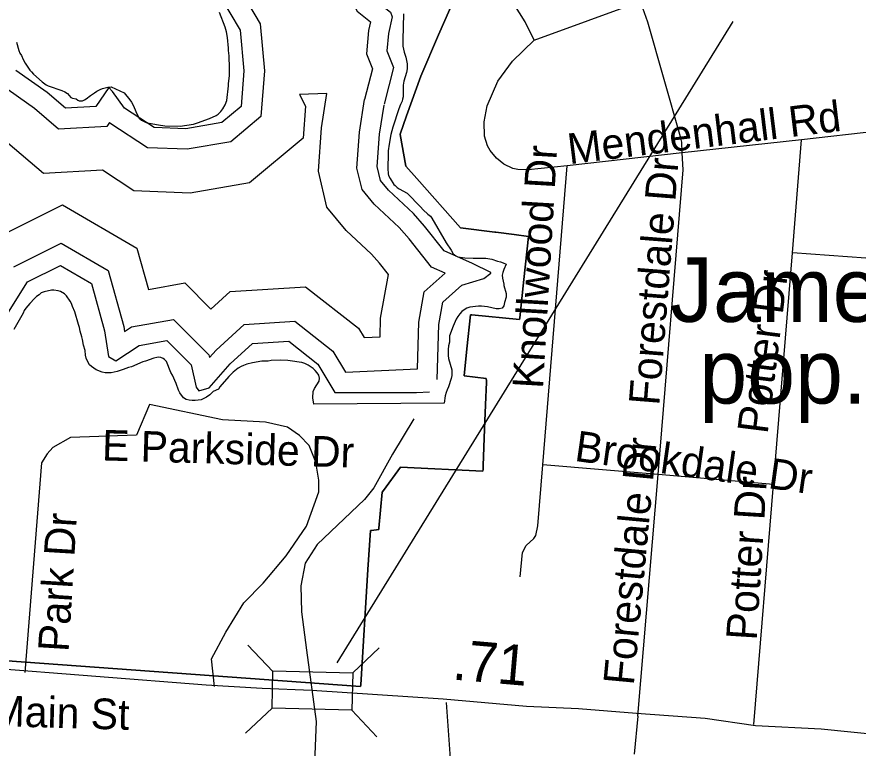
# Model space of a CAD drawing. Extents: x 1662474 to 1856135, y 779280 to 917889.
# Drawn here: x 1719362 to 1721976, y 817423 to 819694 of the extents above; entities that cross this region are included whole.
import ezdxf

# ---------------------------------------------------------------- set-up
doc = ezdxf.new("R2010")
doc.units = 0
for name, color, linetype in [('Exist Boundary Political City Limit New', 7, 'Continuous'), ('Exist Civil Demographics City Label', 7, 'Continuous'), ('Exist Hydrographic Buffer Line', 7, 'Continuous'), ('Exist Hydrographic Creek Single Shore', 7, 'Continuous'), ('Exist Hydrographic Lake Shore', 7, 'Continuous'), ('Exist Road Non-System Type 51', 7, 'Continuous'), ('Exist Road Non-System Type 51 Label', 7, 'Continuous'), ('Exist Road Secondary Mileage Hundredths English Label', 7, 'Continuous'), ('Exist Road Secondary Structure Standard Bridge CELL', 7, 'Continuous'), ('Exist Road Secondary Structure Standard Bridge Number Label', 7, 'Continuous'), ('Exist Road Secondary Type 51 Attributed', 7, 'Continuous'), ('Exist Road Secondary Type 51 Label', 7, 'Continuous'), ('Map Preparation Boundary City Limit Buffer Line', 7, 'Continuous')]:
    doc.layers.add(name, color=color, linetype=linetype)

msp = doc.modelspace()

# ---------------------------------------------------------------- linework, layer by layer
at = {"layer": 'Exist Boundary Political City Limit New'}
msp.add_line((1720751.4, 818579.8), (1720820.2, 818571.1), dxfattribs=at)
for points in [[(1720669.6, 819746.7), (1720704.5, 819719.3), (1720706.5, 819717.7), (1720672.1, 819637.8), (1720617.2, 819509.8), (1720572.8, 819386.3), (1720552.5, 819329.5), (1720552.5, 819328.8), (1720570.4, 819230.3), (1720603.9, 819192.4), (1720739.8, 819039.2), (1720847, 819025.5), (1720850.1, 819025.1), (1720906.6, 819017.9), (1720951.5, 819012.1), (1720951.5, 819011.5), (1720937, 818878.5), (1720924.1, 818759.4), (1720923.5, 818753.9), (1720774.8, 818768.9), (1720771.4, 818769.2), (1720760.2, 818663.7), (1720751.4, 818579.8)], [(1720751.4, 818579.8), (1720760.2, 818663.7), (1720771.4, 818769.2), (1720774.8, 818768.9), (1720923.5, 818753.9), (1720924.1, 818759.4), (1720937, 818878.5), (1720951.5, 819011.5), (1720951.5, 819012.1), (1720906.6, 819017.9), (1720850.1, 819025.1), (1720847, 819025.5), (1720739.8, 819039.2), (1720603.9, 819192.4), (1720570.4, 819230.3), (1720552.5, 819328.8), (1720552.5, 819329.5), (1720572.8, 819386.3), (1720617.2, 819509.8), (1720672.1, 819637.8), (1720706.5, 819717.7), (1720704.5, 819719.3), (1720669.6, 819746.7)], [(1720820.2, 818571.1), (1720821, 818564.1), (1720821, 818563.4), (1720820.9, 818559.7), (1720817.9, 818489.5), (1720814.6, 818413.6), (1720810.6, 818301), (1720810.2, 818289.7), (1720810, 818283.3), (1720554.1, 818295.7), (1720500.8, 818223.8), (1720496.9, 818218.5), (1720486.8, 818106.9), (1720486.4, 818102), (1720463.9, 818099.4), (1720460.1, 818099), (1720452.6, 817978.6), (1720430, 817620.1), (1720429.6, 817614.5), (1719260.4, 817700.1)], [(1719260.4, 817700.1), (1720429.6, 817614.5), (1720430, 817620.1), (1720452.6, 817978.6), (1720460.1, 818099), (1720463.9, 818099.4), (1720486.4, 818102), (1720486.8, 818106.9), (1720496.9, 818218.5), (1720500.8, 818223.8), (1720554.1, 818295.7), (1720810, 818283.3), (1720810.2, 818289.7), (1720810.6, 818301), (1720814.6, 818413.6), (1720817.9, 818489.5), (1720820.9, 818559.7), (1720821, 818563.4), (1720821, 818564.1), (1720820.2, 818571.1)], [(1720820.2, 818571.1), (1720751.4, 818579.2), (1720751.4, 818579.8)]]:
    msp.add_lwpolyline(points, dxfattribs=at)
at = {"layer": 'Exist Hydrographic Buffer Line'}
for points in [[(1720673.8, 820207), (1720589.9, 820190.8), (1720431, 820096.5), (1720352, 819948.2), (1720359.1, 819818.7), (1720419.4, 819711.5), (1720460.1, 819678.6), (1720453.8, 819651.2), (1720448.1, 819579.1), (1720466.2, 819532.9), (1720442.2, 819437.6)], [(1720818.8, 820147.9), (1720765, 820160.9), (1720612.5, 820131.3), (1720478, 820051.6), (1720415.5, 819934.2), (1720420.9, 819836.7), (1720468.1, 819752.7), (1720522.3, 819708.9), (1720527.8, 819693.8), (1720515.9, 819641.7), (1720511.7, 819588.5), (1720531.8, 819537.1), (1720503, 819422.3)], [(1719892.2, 820114.8), (1719923.3, 819961), (1719958.3, 819880.9), (1720041.6, 819800.8), (1720117.8, 819672.6), (1720130.7, 819526.5), (1720120.2, 819384.4), (1720026.1, 819306), (1719890.9, 819282.6), (1719767.9, 819287.6), (1719651, 819363.9), (1719649.7, 819365.6), (1719641.3, 819353.6), (1719490.9, 819345.2), (1719416.5, 819409), (1719309.1, 819484.6)], [(1719831.3, 820095), (1719862.3, 819941.8), (1719905.1, 819843.9), (1719991.3, 819760.9), (1720055.7, 819652.5), (1720066.9, 819526), (1720058.7, 819416), (1719998.4, 819365.7), (1719886.7, 819346.5), (1719788, 819350.4), (1719695.8, 819410.6), (1719659.2, 819461.7), (1719647.6, 819474.4), (1719606.7, 819415.3), (1719512.9, 819410.1), (1719455.6, 819459.3), (1719358.3, 819527.7)], [(1720324.9, 819456.2), (1720240, 819453.2), (1720258.1, 819416.2), (1720250.8, 819317.3), (1720084.8, 819178.9), (1719899.7, 819147), (1719725.3, 819153.9), (1719628, 819217.4), (1719444.1, 819207.2), (1719333.3, 819302.2), (1719204.5, 819392.9), (1719175.7, 819447.9), (1719098, 819494.6)], [(1720490.2, 818700.2), (1720492, 818758.1), (1720516.6, 818893.5), (1720488.9, 818928.7), (1720463.7, 818957.5), (1720385.2, 819030.8), (1720324.8, 819102.8), (1720298.7, 819214.8), (1720308, 819349.7), (1720324.9, 819456.2)], [(1720606.1, 818600.6), (1720610.5, 818745.6), (1720627.7, 818840.6), (1720692, 818897.8), (1720649.7, 818916.3), (1720580.4, 819004.6), (1720549.2, 819040.2), (1720471.6, 819112.7), (1720434.1, 819157.4), (1720418.5, 819224.5), (1720426.1, 819336.3), (1720442.2, 819437.6)], [(1720667.5, 818567.5), (1720672.7, 818739.1), (1720685.2, 818808.3), (1720744.4, 818860.8), (1720812.3, 818881.8), (1720834.4, 818898.3), (1720834.1, 818900.1), (1720777.5, 818928.4), (1720689.1, 818967.1), (1720628.4, 819044.4), (1720594.1, 819083.7), (1720516.9, 819155.7), (1720491.5, 819186.1), (1720481.3, 819229.5), (1720488.2, 819329.3), (1720502.5, 819419.6)], [(1719184, 818848.4), (1719278.8, 818998.5), (1719503.1, 819110.7), (1719734.7, 818975.6), (1719770.6, 818847.1), (1719883.5, 818867.7), (1719964.5, 818786.5), (1720024.9, 818841.4), (1720259, 818856), (1720423.3, 818726.9), (1720440.7, 818697.9), (1720490.2, 818700.2)], [(1719351.8, 818917.8), (1719499.3, 818991.6), (1719645.2, 818906.5), (1719693.9, 818732.2), (1719696.4, 818716.9), (1719718.2, 818731.1), (1719848.2, 818754.7), (1719958.6, 818644.2), (1719960.4, 818636.4), (1719980.6, 818659.4), (1720068.2, 818739.1), (1720225.7, 818748.9), (1720343.3, 818656.4), (1720383, 818590.4), (1720606.1, 818600.6)], [(1719324.9, 818760.8), (1719394.3, 818870.9), (1719497.1, 818922.3), (1719593.1, 818866.2), (1719634.2, 818719.2), (1719646.9, 818639), (1719668.7, 818626.3), (1719741.2, 818673.2), (1719827.6, 818688.9), (1719903.1, 818613.4), (1719919.1, 818543.7), (1719927.1, 818533), (1719959, 818542.1), (1720024.2, 818616.6), (1720093.4, 818679.5), (1720206.2, 818686.6), (1720296.8, 818615.4), (1720349.4, 818527.7), (1720603.8, 818528.1)], [(1720603.8, 818528.1), (1720643.6, 818529.9)]]:
    msp.add_lwpolyline(points, dxfattribs=at)
at = {"layer": 'Exist Hydrographic Creek Single Shore'}
msp.add_lwpolyline([(1720595.1, 818446.1), (1720529, 818336.6), (1720470.8, 818231.6), (1720441.9, 818195.2), (1720295.1, 818056.1), (1720257.4, 817997.8), (1720244.5, 817927.4), (1720245.8, 817846.9), (1720261.2, 817727.4), (1720291.2, 817506.4), (1720286.2, 817379.2), (1720266.5, 817276.2), (1720266.5, 817189.7), (1720281, 817140.1), (1720323.8, 817065.8), (1720400.6, 816997.3), (1720467.9, 816925.6), (1720527.6, 816868.1), (1720565.8, 816818.8), (1720653.9, 816565.6), (1720766.8, 816309.4), (1720794.4, 816154.8)], dxfattribs=at)
at = {"layer": 'Exist Hydrographic Lake Shore'}
for points in [[(1719360.8, 819615.3), (1719367.9, 819589.4), (1719371, 819581.2), (1719376.2, 819573.9), (1719381.5, 819561.2), (1719387.5, 819549.8), (1719401.8, 819528.4), (1719406.8, 819522.7), (1719413.5, 819515.6), (1719440.2, 819492), (1719452.9, 819482.6), (1719458.6, 819479.4), (1719501.1, 819465.2), (1719510.9, 819461), (1719519.2, 819455.5), (1719529.8, 819443.9), (1719534.2, 819441.1), (1719545.5, 819439.5), (1719551.6, 819434.8), (1719555.2, 819433.2), (1719560.2, 819432.7), (1719566, 819433.4), (1719571.8, 819435.8), (1719577.2, 819439.2), (1719590.6, 819450.2), (1719602.8, 819458.4), (1719610.4, 819462.9), (1719620.1, 819468.1), (1719628.2, 819471.5), (1719635.9, 819473.9), (1719644.2, 819475.7), (1719654.8, 819477), (1719695.1, 819458.1), (1719712.2, 819436.6), (1719717.5, 819429), (1719724, 819418), (1719730.9, 819400.4), (1719737.4, 819386.5), (1719742.1, 819379.4), (1719749.2, 819373.1), (1719756.9, 819368.9), (1719763.6, 819366.2), (1719772.6, 819363.9), (1719801.8, 819358.4), (1719821.9, 819355.8), (1719868.6, 819355), (1719889.4, 819357.1), (1719910.6, 819360.8), (1719923.2, 819364.7), (1719959.8, 819378.6), (1719980.5, 819387.5), (1719987.2, 819392), (1719995.6, 819399.6), (1720001.5, 819408.2), (1720009.2, 819420.9), (1720014.5, 819434), (1720019.2, 819479.4), (1720019.2, 819486.8), (1720022.4, 819511.1), (1720022.4, 819534.8), (1720021.4, 819572.6), (1720019, 819589.4), (1720019.2, 819596.4), (1720016.4, 819629.8), (1720013, 819647.4), (1720009, 819662.3), (1719991.8, 819707.8)], [(1720563.1, 819702.8), (1720560.5, 819622.4), (1720561.2, 819603), (1720562.9, 819593.6), (1720565.2, 819584.4), (1720570.5, 819568.6), (1720574.1, 819548.1), (1720574.1, 819532.9), (1720572, 819520.9), (1720563.6, 819494.6), (1720562, 819482), (1720561.5, 819445.8), (1720560.2, 819437.9), (1720558.4, 819432.1), (1720553.6, 819421.9), (1720548.4, 819408.8), (1720529.5, 819351.1), (1720523.5, 819329), (1720518.5, 819299.1), (1720515.6, 819278.1), (1720515.1, 819254.4), (1720513.8, 819238.4), (1720514, 819223.2), (1720515.1, 819206.7), (1720516.9, 819201.4), (1720521.1, 819191.8), (1720532.9, 819173.9), (1720536.6, 819170.2), (1720542.9, 819164.4), (1720549.5, 819160.2), (1720574.4, 819146.9), (1720616.1, 819103.8), (1720623.8, 819094.9), (1720638.8, 819081.2), (1720646.9, 819074.7), (1720651, 819068.9), (1720695.4, 818992), (1720710.6, 818969.7), (1720717.8, 818958.1), (1720721.1, 818955), (1720725.9, 818951.8), (1720732.1, 818949.2), (1720753.9, 818945.6), (1720779.6, 818944.5), (1720809.5, 818944.8), (1720819, 818944.2), (1720837.9, 818941.1), (1720855.2, 818935.8), (1720864.4, 818933.4), (1720873.1, 818930.6), (1720881.8, 818926.1), (1720874.4, 818909.6), (1720871.2, 818900.7), (1720869.9, 818891.8), (1720870.2, 818883.1), (1720874.4, 818864.4), (1720874.9, 818860), (1720881.5, 818835.3), (1720881.8, 818823.2), (1720877, 818806.7), (1720875.1, 818797.2), (1720869.1, 818789.4), (1720860.5, 818787), (1720851, 818787.2), (1720824.5, 818793.6), (1720805.6, 818795.7), (1720796.4, 818795.7), (1720768.6, 818792.2), (1720759.8, 818789.1), (1720751.5, 818784.4), (1720744, 818778.6), (1720737.9, 818771.5), (1720732.1, 818763.4), (1720727.1, 818755.2), (1720717.4, 818734), (1720705.6, 818703.6), (1720705.9, 818684.1), (1720703, 818672.1)], [(1719430.6, 818830.6), (1719423, 818825.3), (1719416.1, 818819.1), (1719401.8, 818803.6), (1719389.9, 818789.9), (1719384.4, 818781.8), (1719380.8, 818773.6), (1719352.4, 818723.5)], [(1719476.5, 818845.8), (1719469.1, 818845), (1719446.6, 818840.6), (1719437.6, 818836.6), (1719430.6, 818830.6)], [(1720703, 818672.1), (1720701.6, 818661.6), (1720701.4, 818651.6), (1720701.6, 818642.9), (1720703, 818633.5), (1720707.5, 818615.1), (1720712.8, 818597.8), (1720713.2, 818589.1), (1720713, 818580.2), (1720711.4, 818571.2), (1720703, 818544.8), (1720698.8, 818536.1), (1720695.6, 818527.4), (1720692.8, 818517.8), (1720689, 818494.6), (1720284.9, 818491.5), (1720280.8, 818511.2), (1720282, 818531.1), (1720286.2, 818539.8), (1720300.9, 818563.1), (1720302, 818571.8), (1720300.1, 818581), (1720294.6, 818588.9), (1720288.2, 818596.2), (1720282, 818602.5), (1720266.5, 818612.8), (1720256.5, 818617.8), (1720247.1, 818620.4), (1720238.5, 818622.2), (1720217.8, 818624.6), (1720203.2, 818626.9), (1720180.8, 818627.9), (1720151.6, 818626.6), (1720142.4, 818625.3), (1720132.9, 818625.3), (1720123.2, 818624.6), (1720094.1, 818620.1), (1720075.8, 818615.6), (1720066.2, 818611.9), (1720058.1, 818608.2), (1720049.8, 818603.3), (1720034.2, 818590.7), (1720026.4, 818583.6), (1720019.8, 818576.8), (1719992.5, 818545.6), (1719988.4, 818538.2), (1719971.8, 818530.6), (1719961.2, 818520.9), (1719950.8, 818513), (1719942.6, 818508.6), (1719934.2, 818504.6), (1719915.9, 818502.5), (1719906.4, 818502.5), (1719897, 818503.8), (1719887.8, 818506.4), (1719879.4, 818510.9), (1719867.9, 818526.4), (1719863.9, 818534.5), (1719856.5, 818555.2), (1719844.8, 818581.2), (1719840, 818589.6), (1719826.6, 818623.5), (1719820.9, 818629.8), (1719816.1, 818633.5), (1719809.4, 818636.4), (1719802.2, 818636.9), (1719797, 818636.4), (1719787.2, 818634), (1719761.8, 818624.8), (1719753.1, 818622.7), (1719718, 818606.9), (1719709, 818604.9), (1719691.8, 818598.6), (1719673.4, 818593.1), (1719655.2, 818588.3), (1719645.5, 818588.3), (1719636.4, 818589.1), (1719626.4, 818591.2), (1719607.8, 818597.8), (1719593.2, 818608.6), (1719587.8, 818613.8), (1719581.5, 818624.6), (1719577.2, 818634.5), (1719574.6, 818643.4), (1719573.4, 818657.6), (1719568.9, 818674.1), (1719566, 818692), (1719563.9, 818700.9), (1719558.6, 818718.5), (1719556.6, 818729), (1719552.9, 818739), (1719541.4, 818777.8), (1719535, 818794.9), (1719531.4, 818803.6), (1719526.9, 818811.7), (1719516.4, 818827.7), (1719510.1, 818834.2), (1719497.5, 818841.6), (1719489.9, 818843.4), (1719476.5, 818845.8)]]:
    msp.add_lwpolyline(points, dxfattribs=at)
at = {"layer": 'Exist Road Non-System Type 51'}
for p, q in [((1720968.6, 819621.9), (1721304.9, 819743.9)), ((1722529.8, 819394.9), (1721799.6, 819312.2)), ((1721799.6, 819312.2), (1721428.9, 819271.5)), ((1721772, 818961), (1721799.6, 819312.2)), ((1721428.9, 819271.5), (1721071.5, 819231.6)), ((1720995.9, 818302.8), (1721071.5, 819231.6)), ((1721712.1, 818242.4), (1721772, 818961)), ((1721353.9, 818272.6), (1720995.9, 818302.8)), ((1721291.6, 817523.2), (1721353.9, 818272.6)), ((1721712.1, 818242.4), (1721353.9, 818272.6)), ((1721651, 817496.8), (1721712.1, 818242.4))]:
    msp.add_line(p, q, dxfattribs=at)
for points in [[(1720968.6, 819621.9), (1720941.4, 819678.4), (1720906.1, 819734.2), (1720861.2, 819783.6), (1720791.4, 819854.4), (1720738.4, 819908.5)], [(1721428.9, 819271.5), (1721427.4, 819304.6), (1721423.6, 819321.6), (1721322.6, 819677.5), (1721301.4, 819735.8), (1721304.9, 819743.9)], [(1721071.5, 819231.6), (1720949.9, 819218.5), (1720918.5, 819219.8), (1720903.2, 819223.2), (1720874.6, 819236.4), (1720851.5, 819254.7), (1720831.9, 819279.4), (1720824, 819293.2), (1720814.8, 819323.2), (1720813.2, 819367.9), (1720823.4, 819417.9), (1720856, 819494.1), (1720901.9, 819556.2), (1720968.6, 819621.9)], [(1721353.9, 818272.6), (1721431.6, 819218.5), (1721428.9, 819271.5)], [(1722546.8, 819004.1), (1721999.6, 818944.5), (1721772, 818961)], [(1719976, 817615.1), (1719966.5, 817700.9), (1720010.9, 817783.6), (1720066.5, 817874.2), (1720126.6, 817935.9), (1720198, 818020.6), (1720261.5, 818112.8), (1720300.1, 818219), (1720300.1, 818255.5), (1720290.4, 818311.4), (1720269.4, 818363.1), (1720240.2, 818394.1), (1720203, 818419.9), (1720134.2, 818435.6), (1720000.9, 818442.9), (1719774.1, 818490.9), (1719733.4, 818395.4), (1719528.1, 818387.8), (1719473.1, 818356.6), (1719456.2, 818336.9), (1719438.6, 818309.6), (1719386.5, 817657.9)], [(1720925.2, 817955), (1720932.4, 818031.4), (1720944.1, 818052.4), (1720967.6, 818074.4), (1720974.4, 818084.1), (1720979.9, 818113.8), (1720995.9, 818302.8)], [(1720695.9, 817565), (1720710.6, 817347.7), (1720726.4, 817237.2), (1720823.8, 816857.6), (1720841, 816792), (1720848.8, 816774.2), (1720869.6, 816756.1), (1720894.1, 816750.9), (1720983, 816775.8), (1721013.5, 816789.7), (1721166.8, 816879.2)], [(1721291.6, 817523.2), (1721279.8, 817404.9)]]:
    msp.add_lwpolyline(points, dxfattribs=at)
at = {"layer": 'Exist Road Secondary Structure Standard Bridge CELL'}
for p, q in [((1720157.4, 817661.1), (1720079.5, 817743.2)), ((1720487.3, 817734.8), (1720405.3, 817656.8)), ((1720154.5, 817548), (1720072.5, 817470)), ((1720480.3, 817459), (1720402.3, 817541.1))]:
    msp.add_line(p, q, dxfattribs=at)
msp.add_lwpolyline([(1720402.3, 817541.1), (1720154.5, 817547.4), (1720157.5, 817663.2), (1720405.3, 817656.8)], close=True, dxfattribs=at)
at = {"layer": 'Exist Road Secondary Structure Standard Bridge Number Label'}
msp.add_line((1720356.8, 817688.5), (1721587.4, 819679.8), dxfattribs=at)
at = {"layer": 'Exist Road Secondary Type 51 Attributed'}
for points in [[(1718639.8, 817717.2), (1718920.8, 817700.7), (1719950.3, 817619.7), (1720123.6, 817610), (1720278.6, 817603.5)], [(1720278.6, 817603.5), (1720686, 817576.4), (1720945.1, 817554), (1721107, 817546.7), (1721287.4, 817532), (1721500.3, 817517), (1721657, 817494), (1721860.4, 817483.1)], [(1721860.4, 817483.1), (1722044.8, 817464.9), (1722202.7, 817456), (1722284.2, 817463.7), (1722321.2, 817469), (1722355.3, 817482.3)]]:
    msp.add_lwpolyline(points, dxfattribs=at)
at = {"layer": 'Map Preparation Boundary City Limit Buffer Line'}
msp.add_line((1720751.4, 818579.8), (1720820.2, 818571.1), dxfattribs=at)
for points in [[(1720669.6, 819746.7), (1720704.5, 819719.3), (1720706.5, 819717.7), (1720672.1, 819637.8), (1720617.2, 819509.8), (1720572.8, 819386.3), (1720552.5, 819329.5), (1720552.5, 819328.8), (1720570.4, 819230.3), (1720603.9, 819192.4), (1720739.8, 819039.2), (1720847, 819025.5), (1720850.1, 819025.1), (1720906.6, 819017.9), (1720951.5, 819012.1), (1720951.5, 819011.5), (1720937, 818878.5), (1720924.1, 818759.4), (1720923.5, 818753.9), (1720774.8, 818768.9), (1720771.4, 818769.2), (1720760.2, 818663.7), (1720751.4, 818579.8)], [(1720751.4, 818579.8), (1720760.2, 818663.7), (1720771.4, 818769.2), (1720774.8, 818768.9), (1720923.5, 818753.9), (1720924.1, 818759.4), (1720937, 818878.5), (1720951.5, 819011.5), (1720951.5, 819012.1), (1720906.6, 819017.9), (1720850.1, 819025.1), (1720847, 819025.5), (1720739.8, 819039.2), (1720603.9, 819192.4), (1720570.4, 819230.3), (1720552.5, 819328.8), (1720552.5, 819329.5), (1720572.8, 819386.3), (1720617.2, 819509.8), (1720672.1, 819637.8), (1720706.5, 819717.7), (1720704.5, 819719.3), (1720669.6, 819746.7)], [(1720820.2, 818571.1), (1720821, 818564.1), (1720821, 818563.4), (1720820.9, 818559.7), (1720817.9, 818489.5), (1720814.6, 818413.6), (1720810.6, 818301), (1720810.2, 818289.7), (1720810, 818283.3), (1720554.1, 818295.7), (1720500.8, 818223.8), (1720496.9, 818218.5), (1720486.8, 818106.9), (1720486.4, 818102), (1720463.9, 818099.4), (1720460.1, 818099), (1720452.6, 817978.6), (1720430, 817620.1), (1720429.6, 817614.5), (1719260.4, 817700.1)], [(1719260.4, 817700.1), (1720429.6, 817614.5), (1720430, 817620.1), (1720452.6, 817978.6), (1720460.1, 818099), (1720463.9, 818099.4), (1720486.4, 818102), (1720486.8, 818106.9), (1720496.9, 818218.5), (1720500.8, 818223.8), (1720554.1, 818295.7), (1720810, 818283.3), (1720810.2, 818289.7), (1720810.6, 818301), (1720814.6, 818413.6), (1720817.9, 818489.5), (1720820.9, 818559.7), (1720821, 818563.4), (1720821, 818564.1), (1720820.2, 818571.1)], [(1720820.2, 818571.1), (1720751.4, 818579.2), (1720751.4, 818579.8)]]:
    msp.add_lwpolyline(points, dxfattribs=at)

# ---------------------------------------------------------------- texts
at = {"layer": 'Exist Civil Demographics City Label'}
for s, p in [('Jamestown', (1721391.1, 818746.9)), ('pop.   3,369', (1721482.2, 818493.3))]:
    msp.add_text(s, height=200, dxfattribs=at).set_placement(p)
at = {"layer": 'Exist Road Non-System Type 51 Label'}
for s, rotation, p in [('Mendenhall Rd', 6.9929, (1721078.5, 819236.2)), ('Knollwood Dr', 86.6118, (1720996.2, 818537.9)), ('Forestdale Dr', 85.4961, (1721357.5, 818485.6)), ('Potter Dr', 82.8008, (1721694.1, 818396.7)), ('E Parkside Dr', 358.3591, (1719625.3, 818316.9)), ('Brookdale Dr', 351.9784, (1721091.8, 818315.7)), ('Forestdale Dr', 84.621, (1721278.3, 817616.7)), ('Potter Dr', 86.358, (1721660.1, 817756.6)), ('Park Dr', 86.4805, (1719522.2, 817720.7))]:
    msp.add_text(s, height=95, rotation=rotation, dxfattribs=at).set_placement(p)
at = {"layer": 'Exist Road Secondary Mileage Hundredths English Label'}
msp.add_text('.71', height=125, rotation=355.0737, dxfattribs=at).set_placement((1720712.4, 817636.8))
at = {"layer": 'Exist Road Secondary Type 51 Label'}
msp.add_text('W Main St', height=95, rotation=358.3624, dxfattribs=at).set_placement((1719124.4, 817497))

doc.saveas('drawing.dxf')
